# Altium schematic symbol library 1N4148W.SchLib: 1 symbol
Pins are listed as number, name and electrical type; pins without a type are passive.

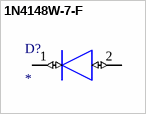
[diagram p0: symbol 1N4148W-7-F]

## 1N4148W-7-F
designator D?
DIODE, SWITCH, 300MA, 100V,SOD123; Diode Configuration:Single; Repetitive Reverse Voltage Vrrm Max:100V; Forward Current If(AV):300mA; Forward Voltage VF Max:1.25V; Reverse Recovery Time trr Max:4ns; Forward Surge Current Ifsm Max:2A; Operating Temperature Max:150Â°C; Diode Case Style:SOD-123; No. of Pins:2Pins; Product Range:1N4148 Series; Automotive Qualification Standard:-; SVHC:No SVHC (15-Jan-2019); Diode Type:Switching; Operating Temperature Min:-65Â°C; Operating Temperature Range:-65Â°C to +150Â°C; MF: Diodes Incorporated; MP: 1N4148W7F
footprint 1N4148W
pins: 1 K (io), 2 A (io)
